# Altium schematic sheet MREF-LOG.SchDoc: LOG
size A4; CompanyName: TRINAMIC; DocumentNumber: 5; SheetNumber: 5; SheetTotal: 5; Author: Indrek Rebane; DrawnBy: Indrek Rebane; Engineer: Indrek Rebane; Organization: Hedgehog OÜ; Address1: Waterloohain 5; Address2: 22769 Hamburg; Address3: Germany; Address4: tmc_info@trinamic.com
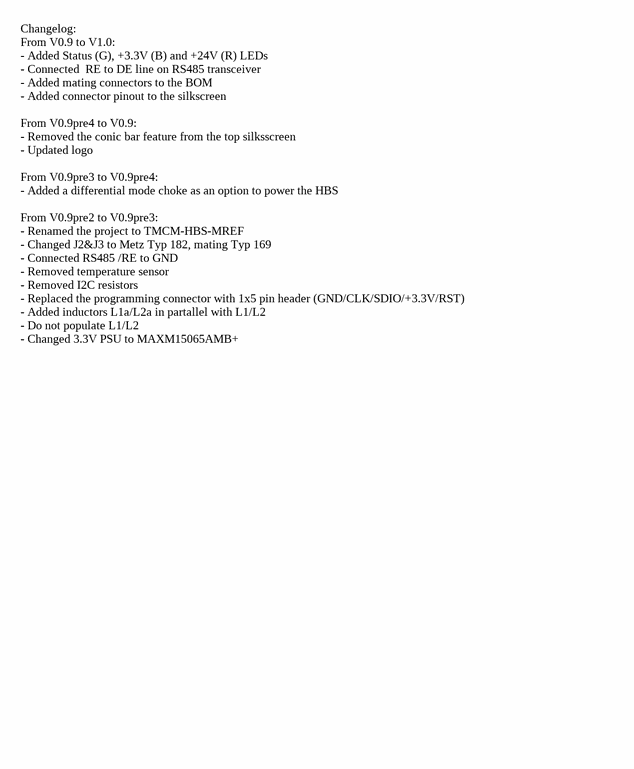
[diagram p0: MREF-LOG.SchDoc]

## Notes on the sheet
- Changelog:
  From V0.9 to V1.0:
  - Added Status (G), +3.3V (B) and +24V (R) LEDs
  - Connected  RE to DE line on RS485 transceiver
  - Added mating connectors to the BOM
  - Added connector pinout to the silkscreen
  From V0.9pre4 to V0.9:
  - Removed the conic bar feature from the top silksscreen
  - Updated logo
  From V0.9pre3 to V0.9pre4:
  - Added a differential mode choke as an option to power the HBS
  From V0.9pre2 to V0.9pre3:
  - Renamed the project to TMCM-HBS-MREF
  - Changed J2&J3 to Metz Typ 182, mating Typ 169
  - Connected RS485 /RE to GND
  - Removed temperature sensor
  - Removed I2C resistors
  - Replaced the programming connector with 1x5 pin header (GND/CLK/SDIO/+3.3V/RST)
  - Added inductors L1a/L2a in partallel with L1/L2
  - Do not populate L1/L2
  - Changed 3.3V PSU to MAXM15065AMB+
